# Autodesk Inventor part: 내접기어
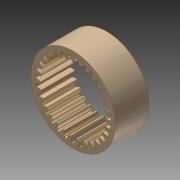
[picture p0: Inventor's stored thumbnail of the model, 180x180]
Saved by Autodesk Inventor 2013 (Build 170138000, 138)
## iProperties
Created: 2023-11
Part Number: 내접기어
Material: 알루미늄 6061
Document SubType Name: Modeling
Designer: mdu-01
Density: 1 g/cm^3
Author: mdu-01
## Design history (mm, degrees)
sketch "스케치1" dims "d0" = 75, "d1" = 62, "d3" = 2.5
  geometry: L1 (0, 0)-(0, 37.5); A1 r 29 centre (0, 0) between (0.57, 28.994) and (-0.57, 28.994); A2 r 8.747 centre (-6.664, 33.911) between (0.57, 28.994) and (2.07, 33.436); A3 r 8.747 centre (6.664, 33.911) between (-2.07, 33.436) and (-0.57, 28.994); A4 r 33.5 centre (0, 0) between (2.07, 33.436) and (-2.07, 33.436); 3 further points
  constraints: 9 point on circle, 4 centre point, 3 coincident, 3 symmetric about line, 2 end point, 1 vertical, 1 vertical alignment, 9 other
  dimensions: "d2" = 2 dimension on A1; "d4" = 1.57 distance from line of point (1.57, 30.96) L1; "d5" = 1 horizontal distance of A1.start point (1.57, 30.96); "d6" = 0.5 horizontal distance of A2.end point (1.57, 30.96)
extrude "돌출1" new body sketch "스케치1" distance "d7" = 30; taper "d8" = 0 deg
extrude "돌출2" join sketch "스케치1" distance "d9" = 30; taper "d10" = 0 deg
fillet "모깎기1" dims "d11" = 0.25
node "솔리드1"
pattern_circular "원형 패턴1" dims angle "d13" = 360 deg
